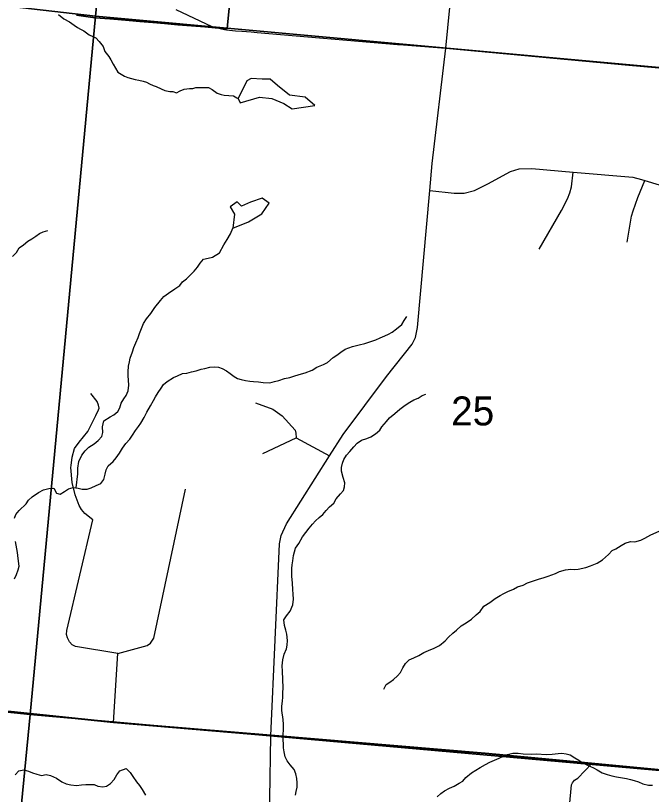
# Model space of a CAD drawing. Extents: x 0 to 34, y -3.9 to 26.2.
# Drawn here: x 3.859 to 4.778, y 17.142 to 18.269 of the extents above; entities that cross this region are included whole.
import ezdxf

# ---------------------------------------------------------------- set-up
doc = ezdxf.new("R2010")
doc.units = 0
for name, color, linetype in [('GM_X_City_Street', 7, 'Continuous'), ('GM_X_Corporation', 7, 'Continuous'), ('GM_X_County_Road', 7, 'Continuous'), ('GM_X_Interstate_Route', 7, 'Continuous'), ('GM_X_Minor_Lake', 7, 'Continuous'), ('GM_X_Minor_River', 7, 'Continuous'), ('GM_X_Section', 7, 'Continuous'), ('GM_X_Section_Text', 7, 'Continuous')]:
    doc.layers.add(name, color=color, linetype=linetype)

msp = doc.modelspace()

# ---------------------------------------------------------------- linework, layer by layer
at = {"layer": 'GM_X_City_Street'}
for p, q in [((4.2162, 17.6352), (4.2646, 17.6578)), ((4.0008, 17.2463), (4.0071, 17.3458))]:
    msp.add_line(p, q, dxfattribs=at)
for points in [[(4.4578, 18.0157), (4.4928, 18.0116), (4.5072, 18.0116), (4.5221, 18.0158), (4.5413, 18.0251), (4.5744, 18.0432), (4.587, 18.0471), (4.6052, 18.0477), (4.665, 18.0424), (4.7509, 18.0347), (4.7637, 18.0317), (4.7684, 18.0302), (4.8051, 18.0188), (4.8146, 18.0174), (4.8283, 18.0186), (4.8851, 18.0181)], [(4.6159, 17.9309), (4.6481, 17.9866), (4.6565, 18.0034), (4.6602, 18.0123), (4.6622, 18.0211), (4.665, 18.0424)], [(4.7428, 17.9408), (4.7491, 17.9786), (4.7513, 17.9864), (4.7581, 18.0057), (4.7684, 18.0302)], [(3.9707, 17.5393), (3.9591, 17.5483), (3.9545, 17.5542), (3.9511, 17.5603), (3.945, 17.5753), (3.9409, 17.5932), (3.9392, 17.6148), (3.9393, 17.6179), (3.941, 17.6301), (3.9441, 17.6425), (3.9508, 17.6518), (3.9637, 17.667), (3.9753, 17.6902), (3.9791, 17.6982), (3.9797, 17.7008), (3.9791, 17.7054), (3.9769, 17.7107), (3.9677, 17.722)], [(4.2056, 17.7084), (4.2307, 17.6994), (4.2378, 17.6946), (4.2445, 17.6899), (4.2633, 17.6689), (4.264, 17.6647), (4.2646, 17.6578), (4.3129, 17.6317)], [(4.0071, 17.3458), (4.0491, 17.3576), (4.0541, 17.3609), (4.0588, 17.3684), (4.1049, 17.5835)], [(4.0071, 17.3458), (3.9459, 17.3562), (3.9408, 17.3588), (3.937, 17.3629), (3.934, 17.3689), (3.9328, 17.3735), (3.9332, 17.3793), (3.9707, 17.5393)], [(4.561, 16.6819), (4.5624, 16.71), (4.5649, 16.7656), (4.5696, 16.8742), (4.5697, 16.8749), (4.575, 16.9128), (4.5757, 16.9173), (4.6327, 16.9229), (4.6377, 16.9258), (4.6416, 16.9314), (4.6625, 17.156), (4.664, 17.1591), (4.667, 17.1627), (4.6716, 17.1659), (4.6916, 17.1869)]]:
    msp.add_lwpolyline(points, dxfattribs=at)
at = {"layer": 'GM_X_Corporation'}
for points in [[(3.947, 18.269), (3.9742, 18.2656), (3.9953, 18.2638), (4.0179, 18.2618), (4.0388, 18.26), (4.0574, 18.2585), (4.0741, 18.2571), (4.0937, 18.2554), (4.1195, 18.2533), (4.1325, 18.2522), (4.1476, 18.2509), (4.1649, 18.2494), (4.1653, 18.2549), (4.1714, 18.3184)], [(4.1714, 18.3184), (4.1653, 18.2549), (4.1649, 18.2494), (4.1476, 18.2509), (4.1325, 18.2522), (4.1195, 18.2533), (4.0937, 18.2554), (4.0741, 18.2571), (4.0574, 18.2585), (4.0388, 18.26), (4.0179, 18.2618), (3.9953, 18.2638), (3.9742, 18.2656), (3.947, 18.269)]]:
    msp.add_lwpolyline(points, dxfattribs=at)
at = {"layer": 'GM_X_County_Road'}
msp.add_line((4.1994, 18.2449), (4.2082, 18.2441), dxfattribs=at)
for points in [[(4.2282, 17.2272), (4.2405, 17.5046), (4.243, 17.5167), (4.2505, 17.5336), (4.3129, 17.6317), (4.3327, 17.663), (4.3951, 17.7468), (4.4324, 17.7935), (4.4372, 17.8029), (4.4401, 17.8177), (4.4578, 18.0157), (4.4613, 18.0547), (4.4809, 18.2213), (4.5117, 18.5353), (4.5194, 18.6193)], [(4.0908, 18.2775), (4.1427, 18.2527), (4.1547, 18.2497), (4.1611, 18.2484), (4.1637, 18.2481)], [(4.1637, 18.2481), (4.1769, 18.2468), (4.1862, 18.246), (4.1994, 18.2449)], [(4.2082, 18.2441), (4.4108, 18.227), (4.4196, 18.2263)], [(4.4196, 18.2263), (4.4809, 18.2213), (4.7454, 18.1968), (4.8976, 18.1834), (5.0316, 18.1703), (5.1666, 18.1558), (5.2076, 18.1513)], [(3.3516, 17.3145), (3.3738, 17.3124), (3.4729, 17.3017), (3.6511, 17.2821), (3.7277, 17.2747), (4.0008, 17.2463), (4.2282, 17.2272)], [(4.2877, 16.7458), (4.2695, 16.7971), (4.2692, 16.7985), (4.2577, 16.855), (4.2532, 16.8791), (4.2517, 16.9194), (4.2524, 16.9559), (4.2525, 16.9588), (4.2531, 16.9733), (4.2502, 16.9984), (4.238, 17.0543), (4.2327, 17.0786), (4.2296, 17.0926), (4.2259, 17.1155), (4.2263, 17.1364), (4.2282, 17.2272)], [(4.2282, 17.2272), (4.5377, 17.2014), (4.6916, 17.1869), (4.8483, 17.1722), (5.0107, 17.1555), (5.0253, 17.1536), (5.0595, 17.1494)]]:
    msp.add_lwpolyline(points, dxfattribs=at)
at = {"layer": 'GM_X_Interstate_Route'}
for points in [[(2.9486, 18.2958), (2.91, 17.8963), (2.8923, 17.7142), (2.8852, 17.6093), (2.8647, 17.4286), (2.8585, 17.366), (2.8849, 17.3636), (2.9693, 17.3552), (3.0981, 17.3414), (3.1746, 17.3332), (3.2809, 17.3219), (3.3735, 17.3129), (3.4727, 17.3022), (3.6509, 17.2827), (3.7275, 17.2753), (4.0006, 17.2468), (4.2279, 17.2278), (4.5375, 17.2019), (4.6914, 17.1875), (4.8481, 17.1727)], [(4.8481, 17.1727), (4.6914, 17.1875), (4.5375, 17.2019), (4.2279, 17.2278), (4.0006, 17.2468), (3.7275, 17.2753)]]:
    msp.add_lwpolyline(points, dxfattribs=at)
at = {"layer": 'GM_X_Minor_Lake'}
for points in [[(4.181, 18.1489), (4.1835, 18.1426), (4.2114, 18.1504), (4.2296, 18.1489), (4.2466, 18.1413), (4.259, 18.1339), (4.2917, 18.1385), (4.2775, 18.1506), (4.2548, 18.1537), (4.2376, 18.1677), (4.2271, 18.1767), (4.2154, 18.1769), (4.1994, 18.1776), (4.1933, 18.1743)], [(4.1933, 18.1743), (4.181, 18.1489)], [(4.1729, 17.9611), (4.1957, 17.9702), (4.2149, 17.982), (4.2255, 17.9974), (4.2154, 18.0044), (4.1985, 17.9987), (4.1855, 17.9932), (4.1791, 17.9991), (4.1691, 17.992), (4.1754, 17.9813)], [(4.1754, 17.9813), (4.1729, 17.9611)]]:
    msp.add_lwpolyline(points, dxfattribs=at)
at = {"layer": 'GM_X_Minor_River'}
for points in [[(3.921, 18.2703), (3.9291, 18.2639), (3.9369, 18.2594), (3.944, 18.2549), (3.9484, 18.2513), (3.9528, 18.2492), (3.9577, 18.2468), (3.9654, 18.2407), (3.9751, 18.2365), (3.9799, 18.231), (3.9857, 18.2239), (3.988, 18.2166), (3.9938, 18.2095), (3.9967, 18.2045), (4.0002, 18.1982), (4.0034, 18.1928), (4.007, 18.1866), (4.0115, 18.1837), (4.0163, 18.1809), (4.0215, 18.1791), (4.0321, 18.1764), (4.0373, 18.1754), (4.0434, 18.1737), (4.0482, 18.1723), (4.0527, 18.1698), (4.0579, 18.1677), (4.0624, 18.166), (4.0695, 18.1627), (4.0747, 18.1602), (4.0819, 18.1588), (4.0865, 18.1586), (4.0917, 18.1568), (4.0972, 18.16), (4.1026, 18.1621), (4.1106, 18.1633), (4.1151, 18.1631), (4.1198, 18.1644), (4.1243, 18.1646), (4.1319, 18.1647), (4.138, 18.1644), (4.1432, 18.1619), (4.1506, 18.1563), (4.1562, 18.1545), (4.1607, 18.1536), (4.1672, 18.1529), (4.174, 18.1527), (4.1788, 18.1498), (4.181, 18.1489)], [(3.8548, 17.9204), (3.8603, 17.9262), (3.8644, 17.9325), (3.8706, 17.9372), (3.8766, 17.9426), (3.8824, 17.9458), (3.8882, 17.9494), (3.8937, 17.9533), (3.8991, 17.9558), (3.9057, 17.9578)], [(3.9466, 17.5854), (3.9492, 17.6059), (3.9491, 17.6139), (3.9503, 17.6237), (3.9548, 17.6327), (3.9596, 17.6389), (3.9651, 17.6444), (3.9726, 17.6494), (3.9784, 17.6541), (3.984, 17.66), (3.9854, 17.6656), (3.9849, 17.674), (3.9868, 17.6827), (3.9958, 17.6884), (4.0012, 17.6912), (4.0067, 17.6959), (4.0096, 17.7015), (4.0117, 17.7082), (4.0154, 17.7142), (4.019, 17.7193), (4.0216, 17.7261), (4.023, 17.734), (4.0225, 17.7412), (4.022, 17.7477), (4.0219, 17.7534), (4.0222, 17.7618), (4.0236, 17.7678), (4.0249, 17.7731), (4.028, 17.7824), (4.0301, 17.7884), (4.033, 17.7951), (4.0364, 17.803), (4.0381, 17.8086), (4.0402, 17.8138), (4.044, 17.8232), (4.0481, 17.8302), (4.0548, 17.8379), (4.0605, 17.8465), (4.0685, 17.8568), (4.0733, 17.8623), (4.0799, 17.8673), (4.0893, 17.8734), (4.0963, 17.8784), (4.1003, 17.8836), (4.1062, 17.8879), (4.1121, 17.8937), (4.1173, 17.8992), (4.1221, 17.9047), (4.1261, 17.9106), (4.1309, 17.9161), (4.1374, 17.9178), (4.1435, 17.919), (4.1537, 17.9254), (4.1602, 17.9373), (4.1651, 17.9447), (4.1696, 17.9529), (4.1729, 17.9611)], [(4.0652, 17.7235), (4.0696, 17.7298), (4.0728, 17.735), (4.0783, 17.7393), (4.0873, 17.745), (4.0931, 17.7478), (4.1001, 17.7509), (4.1065, 17.7514), (4.1135, 17.7534), (4.12, 17.7547), (4.1273, 17.7574), (4.1327, 17.7583), (4.1396, 17.7603), (4.1472, 17.7604), (4.1525, 17.7602), (4.1577, 17.7584), (4.1641, 17.7547), (4.1692, 17.7511), (4.1748, 17.7467), (4.18, 17.7438), (4.1852, 17.7425), (4.1913, 17.7411), (4.1977, 17.74), (4.203, 17.7394), (4.2102, 17.7388), (4.217, 17.7381), (4.2265, 17.7377), (4.2334, 17.7393), (4.2395, 17.741), (4.2476, 17.7437), (4.2556, 17.7452), (4.261, 17.7469), (4.2687, 17.7493), (4.2776, 17.7519), (4.2876, 17.7557), (4.2946, 17.76), (4.3039, 17.7638), (4.3097, 17.7669), (4.318, 17.7742), (4.3234, 17.7774), (4.3293, 17.7817), (4.3355, 17.7864), (4.346, 17.7901), (4.3555, 17.7924), (4.3636, 17.7943), (4.3725, 17.7974), (4.3798, 17.7998), (4.386, 17.8025), (4.3925, 17.8057), (4.398, 17.8081), (4.4034, 17.8109), (4.4097, 17.8156), (4.4171, 17.8218), (4.4204, 17.8277), (4.4244, 17.8332)], [(3.8577, 17.5417), (3.8595, 17.5469), (3.8643, 17.5528), (3.8745, 17.5623), (3.8778, 17.5678), (3.8833, 17.5726), (3.8923, 17.579), (3.8993, 17.5825), (3.9073, 17.5849), (3.9142, 17.585), (3.9181, 17.578), (3.9237, 17.5766), (3.9296, 17.5805), (3.9354, 17.5841), (3.9423, 17.5861), (3.9495, 17.585), (3.9555, 17.5836), (3.9628, 17.5837), (3.9685, 17.5854), (3.9755, 17.5889), (3.9821, 17.592), (3.9869, 17.5979), (3.9887, 17.6054), (3.9901, 17.6115), (3.993, 17.6174), (4, 17.6236), (4.0044, 17.6291), (4.0093, 17.6357), (4.0137, 17.6428), (4.0186, 17.6498), (4.0241, 17.656), (4.0282, 17.6619), (4.0326, 17.6686), (4.0366, 17.6741), (4.0402, 17.6793), (4.0451, 17.6875), (4.0488, 17.6949), (4.0541, 17.7042), (4.0582, 17.712), (4.0615, 17.7172), (4.0652, 17.7235)], [(4.2634, 17.141), (4.2648, 17.1463), (4.2658, 17.1527), (4.266, 17.1592), (4.2655, 17.1653), (4.2643, 17.1718), (4.2615, 17.1783), (4.256, 17.185), (4.2517, 17.1909), (4.2489, 17.1964), (4.2473, 17.204), (4.2464, 17.2094), (4.2462, 17.2147), (4.2457, 17.2212), (4.2465, 17.2432), (4.2457, 17.2504), (4.2439, 17.2634), (4.2438, 17.2699), (4.2448, 17.2771), (4.2455, 17.2831), (4.2453, 17.2892), (4.2456, 17.2964), (4.2453, 17.3082), (4.2446, 17.3204), (4.2442, 17.328), (4.2453, 17.3367), (4.2471, 17.345), (4.2505, 17.3529), (4.2518, 17.3581), (4.2521, 17.365), (4.2513, 17.3741), (4.2496, 17.3799), (4.2476, 17.3864), (4.2468, 17.3948), (4.2505, 17.4007), (4.2557, 17.4074), (4.2598, 17.4163), (4.2605, 17.4246), (4.2604, 17.4319), (4.2599, 17.4384), (4.2592, 17.4479), (4.2584, 17.4578), (4.2582, 17.4635), (4.2585, 17.4688), (4.259, 17.4741), (4.2597, 17.4802), (4.2607, 17.4877), (4.2624, 17.493), (4.2638, 17.4986), (4.2682, 17.5053), (4.2736, 17.5146), (4.2836, 17.5274), (4.288, 17.533), (4.2923, 17.5381), (4.2978, 17.5428), (4.3033, 17.5471), (4.3077, 17.5527), (4.3129, 17.5582), (4.3188, 17.5636), (4.3225, 17.5695), (4.3284, 17.5769), (4.3328, 17.582), (4.3346, 17.5873), (4.3348, 17.593), (4.3324, 17.6007), (4.3301, 17.6095), (4.3303, 17.6148), (4.3317, 17.6212), (4.3334, 17.6265), (4.3375, 17.6328), (4.3419, 17.6383), (4.3478, 17.6449), (4.3526, 17.6504), (4.3592, 17.6547), (4.3666, 17.657), (4.3727, 17.6594), (4.379, 17.6637), (4.3853, 17.6688), (4.3885, 17.674), (4.3953, 17.6817), (4.3996, 17.6868), (4.4071, 17.693), (4.4142, 17.6995), (4.422, 17.7053), (4.4287, 17.7095), (4.4345, 17.7127), (4.4407, 17.7155), (4.4465, 17.7191), (4.4519, 17.7211)], [(4.3911, 17.2946), (4.3944, 17.3013), (4.3998, 17.3045), (4.4053, 17.3084), (4.4112, 17.3135), (4.4152, 17.3187), (4.4189, 17.3253), (4.4225, 17.3317), (4.4281, 17.3371), (4.4347, 17.3399), (4.442, 17.343), (4.449, 17.3473), (4.4556, 17.3504), (4.4641, 17.3539), (4.4718, 17.3577), (4.4801, 17.3642), (4.4848, 17.3697), (4.4908, 17.3756), (4.4963, 17.3799), (4.503, 17.3861), (4.5104, 17.3903), (4.5178, 17.3957), (4.5245, 17.4019), (4.5304, 17.4066), (4.5356, 17.4144), (4.5442, 17.4197), (4.552, 17.4255), (4.5594, 17.4297), (4.5648, 17.4329), (4.5703, 17.4357), (4.5788, 17.4392), (4.5846, 17.4424), (4.5927, 17.4451), (4.5989, 17.4482), (4.6074, 17.4509), (4.6147, 17.4533), (4.6228, 17.456), (4.6289, 17.458), (4.6393, 17.4617), (4.6451, 17.4645), (4.6536, 17.4669), (4.6616, 17.468), (4.6669, 17.4674), (4.6722, 17.468), (4.683, 17.4702), (4.6899, 17.4729), (4.6996, 17.4767), (4.707, 17.4814), (4.7157, 17.4894), (4.7212, 17.4948), (4.7266, 17.4976), (4.7344, 17.5023), (4.7402, 17.5054), (4.7479, 17.5078), (4.754, 17.5075), (4.7628, 17.5098), (4.7682, 17.5126), (4.7772, 17.5176), (4.7892, 17.5228)], [(3.8577, 17.4539), (3.8606, 17.4602), (3.8628, 17.467), (3.8641, 17.4723), (3.8631, 17.4833), (3.8619, 17.4921), (3.8609, 17.4975), (3.8591, 17.5078)], [(4.4682, 17.1386), (4.4737, 17.1437), (4.4791, 17.1473), (4.4861, 17.1512), (4.4927, 17.1543), (4.5001, 17.1586), (4.5055, 17.1614), (4.5099, 17.1669), (4.5178, 17.1734), (4.5244, 17.1773), (4.5306, 17.1812), (4.538, 17.1855), (4.5446, 17.189), (4.5512, 17.1918), (4.5578, 17.1949), (4.564, 17.1977), (4.5698, 17.2001), (4.5778, 17.2017), (4.5854, 17.2018), (4.5926, 17.2011), (4.6047, 17.2006), (4.612, 17.2007), (4.626, 17.2001), (4.6344, 17.2005), (4.6432, 17.2013), (4.6485, 17.2018), (4.6549, 17.2011), (4.6606, 17.1994), (4.6672, 17.1953), (4.6732, 17.1917), (4.6787, 17.188), (4.6854, 17.1847), (4.694, 17.1805), (4.6996, 17.1776), (4.7067, 17.1735), (4.7138, 17.171), (4.7206, 17.1692)], [(3.8584, 17.1704), (3.8639, 17.1762), (3.8712, 17.1778), (3.8776, 17.1757), (3.8836, 17.1735), (3.8899, 17.1713), (3.8967, 17.1695), (3.9032, 17.1708), (3.9096, 17.1698), (3.9182, 17.1656), (3.926, 17.1603), (3.932, 17.1574), (3.9391, 17.156), (3.9471, 17.1553), (3.9543, 17.1561), (3.9608, 17.1566), (3.9669, 17.1568), (3.9726, 17.1565), (3.9778, 17.154), (3.985, 17.153), (3.9907, 17.1542), (3.9962, 17.1582), (4.0017, 17.1637), (4.0054, 17.1704), (4.0098, 17.1763), (4.0187, 17.1797), (4.0249, 17.1737), (4.0285, 17.1683), (4.0339, 17.1604), (4.0383, 17.1549), (4.0422, 17.1494)], [(4.7206, 17.1692), (4.7273, 17.1677), (4.733, 17.1667), (4.7417, 17.1652), (4.7477, 17.1639), (4.753, 17.1625), (4.7593, 17.1603), (4.7657, 17.1574), (4.7736, 17.1556), (4.7797, 17.1557)], [(4.0422, 17.1494), (4.0468, 17.1413)]]:
    msp.add_lwpolyline(points, dxfattribs=at)
at = {"layer": 'GM_X_Section'}
for points in [[(3.0608, 19.3936), (4.0751, 19.2669), (3.9744, 18.2676), (2.9569, 18.3849)], [(4.0751, 19.2669), (5.0852, 19.1785), (4.9898, 18.1753), (3.9744, 18.2676)], [(2.9569, 18.3849), (3.9744, 18.2676), (3.8804, 17.2579), (2.8603, 17.3639)], [(3.9744, 18.2676), (4.9898, 18.1753), (4.8928, 17.1679), (3.8804, 17.2579)], [(2.8603, 17.3639), (3.8804, 17.2579), (3.7818, 16.2487), (2.7633, 16.3554)], [(3.8804, 17.2579), (4.8928, 17.1679), (4.7847, 16.1582), (3.7818, 16.2487)]]:
    msp.add_lwpolyline(points, close=True, dxfattribs=at)

# ---------------------------------------------------------------- texts
at = {"layer": 'GM_X_Section_Text'}
msp.add_text('25', height=0.04186, rotation=0, dxfattribs=at).set_placement((4.4885, 17.6759))

doc.saveas('drawing.dxf')
